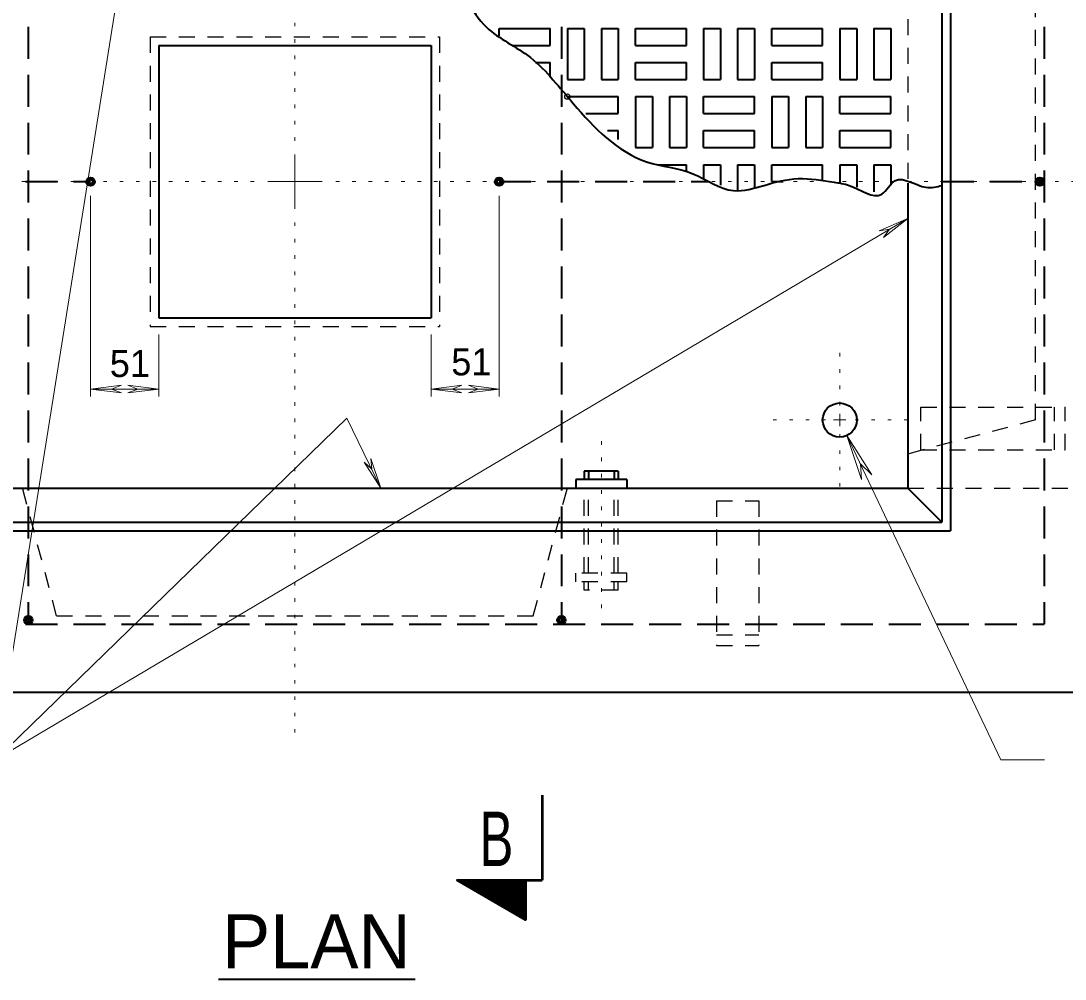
# Model space of a CAD drawing. Extents: x 312583 to 312854, y 144419 to 144597.
# Drawn here: x 312722.24 to 312751.63, y 144519.33 to 144546.3 of the extents above; entities that cross this region are included whole.
import ezdxf
from ezdxf.enums import TextEntityAlignment as Align

# ---------------------------------------------------------------- set-up
doc = ezdxf.new("R2010")
doc.units = 0
doc.header["$LTSCALE"] = 0.3
doc.header["$PDMODE"] = 32
doc.header["$PDSIZE"] = 0.15
for name, pattern in [('DOTTED', [1.5, 0.3, -1.2]), ('MEDIUM_DASHED', [4.5, 3, -1.5]), ('SHORT_DASHED', [2.7, 1.5, -1.2])]:
    doc.linetypes.add(name, pattern=pattern)
doc.layers.add('1', color=7, linetype='Continuous', lineweight=25)
doc.layers.add('2', color=7, linetype='Continuous', lineweight=13)

msp = doc.modelspace()

# ---------------------------------------------------------------- linework, layer by layer
at = {"layer": '1', "linetype": 'MEDIUM_DASHED', "lineweight": 40}
for p, q in [((312722.4474, 144554.2319), (312722.4474, 144529.3153)), ((312737.451, 144554.2319), (312737.451, 144529.3153)), ((312708.8697, 144541.7736), (312724.203, 144541.7736)), ((312735.703, 144541.7736), (312741.5987, 144541.7736)), ((312748.1614, 144541.7736), (312751.0364, 144541.7736)), ((312708.8697, 144529.3153), (312751.0364, 144529.3153))]:
    msp.add_line(p, q, dxfattribs=at)
at = {"layer": '1', "linetype": 'SHORT_DASHED'}
for p, q in [((312747.203, 144550.3986), (312747.203, 144541.7276)), ((312750.791, 144535.0653), (312750.791, 144548.4819)), ((312725.8744, 144545.8446), (312725.8744, 144537.6949)), ((312725.8744, 144537.6949), (312734.024, 144537.6949)), ((312747.5634, 144534.2219), (312747.5634, 144535.4256)), ((312747.5634, 144535.4256), (312751.6267, 144535.4256)), ((312751.3277, 144534.2219), (312751.3277, 144535.4256)), ((312751.6267, 144534.2219), (312751.6267, 144535.4256)), ((312750.791, 144535.0653), (312747.203, 144534.1069)), ((312747.5634, 144534.2219), (312751.6267, 144534.2219)), ((312723.2447, 144529.5529), (312722.2864, 144533.1486)), ((312736.6614, 144529.5529), (312737.6197, 144533.1486)), ((312738.095, 144530.7489), (312738.095, 144533.1486)), ((312738.2177, 144530.7489), (312738.2177, 144533.1486)), ((312738.9384, 144530.7489), (312738.9384, 144533.1486)), ((312739.0534, 144530.7489), (312739.0534, 144533.1486)), ((312747.203, 144533.1486), (312752.953, 144533.1486)), ((312741.8134, 144532.7883), (312743.0094, 144532.7883)), ((312741.8134, 144532.7883), (312741.8134, 144528.7173)), ((312743.0094, 144532.7883), (312743.0094, 144528.7173)), ((312739.291, 144530.7489), (312737.8574, 144530.7489)), ((312737.8574, 144530.5113), (312737.8574, 144530.7489)), ((312739.291, 144530.5113), (312739.291, 144530.7489)), ((312739.291, 144530.5113), (312737.8574, 144530.5113)), ((312738.095, 144530.2736), (312738.095, 144530.5113)), ((312739.0534, 144530.2736), (312738.095, 144530.2736)), ((312738.2177, 144530.2736), (312738.2177, 144530.5113)), ((312738.9384, 144530.2736), (312738.9384, 144530.5113)), ((312739.0534, 144530.2736), (312739.0534, 144530.5113)), ((312723.2447, 144529.5529), (312736.6614, 144529.5529)), ((312741.8134, 144529.0163), (312743.0094, 144529.0163)), ((312741.8134, 144528.7173), (312743.0094, 144528.7173))]:
    msp.add_line(p, q, dxfattribs=at)
at = {"layer": '1', "lineweight": 40}
for p, q in [((312735.703, 144546.0823), (312737.1367, 144546.0823)), ((312735.703, 144545.8753), (312735.703, 144546.0823)), ((312737.1367, 144545.6069), (312737.1367, 144546.0823)), ((312737.6197, 144546.0823), (312737.6197, 144544.6486)), ((312737.6197, 144546.0823), (312738.095, 144546.0823)), ((312738.095, 144546.0823), (312738.095, 144544.6486)), ((312738.578, 144546.0823), (312738.578, 144544.6486)), ((312738.578, 144546.0823), (312739.0534, 144546.0823)), ((312739.0534, 144546.0823), (312739.0534, 144544.6486)), ((312739.5364, 144546.0823), (312740.97, 144546.0823)), ((312739.5364, 144545.6069), (312739.5364, 144546.0823)), ((312740.97, 144545.6069), (312740.97, 144546.0823)), ((312741.453, 144546.0823), (312741.453, 144544.6486)), ((312741.453, 144546.0823), (312741.9284, 144546.0823)), ((312741.9284, 144546.0823), (312741.9284, 144544.6486)), ((312742.4114, 144546.0823), (312742.4114, 144544.6486)), ((312742.4114, 144546.0823), (312742.8867, 144546.0823)), ((312742.8867, 144546.0823), (312742.8867, 144544.6486)), ((312743.3697, 144546.0823), (312744.8034, 144546.0823)), ((312743.3697, 144545.6069), (312743.3697, 144546.0823)), ((312744.8034, 144545.6069), (312744.8034, 144546.0823)), ((312745.2864, 144546.0823), (312745.2864, 144544.6486)), ((312745.2864, 144546.0823), (312745.7617, 144546.0823)), ((312745.7617, 144546.0823), (312745.7617, 144544.6486)), ((312746.2447, 144546.0823), (312746.2447, 144544.6486)), ((312746.2447, 144546.0823), (312746.72, 144546.0823)), ((312746.72, 144546.0823), (312746.72, 144544.6486)), ((312726.1197, 144545.6069), (312726.1197, 144537.9403)), ((312726.1197, 144545.6069), (312733.7864, 144545.6069)), ((312733.7864, 144545.6069), (312733.7864, 144537.9403)), ((312736.094, 144545.6069), (312737.1367, 144545.6069)), ((312739.5364, 144545.6069), (312740.97, 144545.6069)), ((312743.3697, 144545.6069), (312744.8034, 144545.6069)), ((312736.7227, 144545.1239), (312737.1367, 144545.1239)), ((312737.1367, 144544.7099), (312737.1367, 144545.1239)), ((312739.5364, 144545.1239), (312740.97, 144545.1239)), ((312739.5364, 144544.6486), (312739.5364, 144545.1239)), ((312740.97, 144544.6486), (312740.97, 144545.1239)), ((312743.3697, 144545.1239), (312744.8034, 144545.1239)), ((312743.3697, 144544.6486), (312743.3697, 144545.1239)), ((312744.8034, 144544.6486), (312744.8034, 144545.1239)), ((312737.6197, 144544.6486), (312738.095, 144544.6486)), ((312738.578, 144544.6486), (312739.0534, 144544.6486)), ((312739.5364, 144544.6486), (312740.97, 144544.6486)), ((312741.453, 144544.6486), (312741.9284, 144544.6486)), ((312742.4114, 144544.6486), (312742.8867, 144544.6486)), ((312743.3697, 144544.6486), (312744.8034, 144544.6486)), ((312745.2864, 144544.6486), (312745.7617, 144544.6486)), ((312746.2447, 144544.6486), (312746.72, 144544.6486)), ((312737.6197, 144544.1656), (312739.0534, 144544.1656)), ((312739.0534, 144543.6903), (312739.0534, 144544.1656)), ((312739.5364, 144544.1656), (312739.5364, 144542.7319)), ((312739.5364, 144544.1656), (312740.0117, 144544.1656)), ((312740.0117, 144544.1656), (312740.0117, 144542.7319)), ((312740.4947, 144544.1656), (312740.4947, 144542.7319)), ((312740.4947, 144544.1656), (312740.97, 144544.1656)), ((312740.97, 144544.1656), (312740.97, 144542.7319)), ((312741.453, 144544.1656), (312742.8867, 144544.1656)), ((312741.453, 144543.6903), (312741.453, 144544.1656)), ((312742.8867, 144543.6903), (312742.8867, 144544.1656)), ((312743.3697, 144544.1656), (312743.3697, 144542.7319)), ((312743.3697, 144544.1656), (312743.845, 144544.1656)), ((312743.845, 144544.1656), (312743.845, 144542.7319)), ((312744.328, 144544.1656), (312744.328, 144542.7319)), ((312744.328, 144544.1656), (312744.8034, 144544.1656)), ((312744.8034, 144544.1656), (312744.8034, 144542.7319)), ((312745.2864, 144544.1656), (312746.72, 144544.1656)), ((312745.2864, 144543.6903), (312745.2864, 144544.1656)), ((312746.72, 144543.6903), (312746.72, 144544.1656)), ((312738.141, 144543.6903), (312739.0534, 144543.6903)), ((312741.453, 144543.6903), (312742.8867, 144543.6903)), ((312745.2864, 144543.6903), (312746.72, 144543.6903)), ((312738.7467, 144543.2073), (312739.0534, 144543.2073)), ((312739.0534, 144542.9619), (312739.0534, 144543.2073)), ((312741.453, 144543.2073), (312742.8867, 144543.2073)), ((312741.453, 144542.7319), (312741.453, 144543.2073)), ((312742.8867, 144542.7319), (312742.8867, 144543.2073)), ((312745.2864, 144543.2073), (312746.72, 144543.2073)), ((312745.2864, 144542.7319), (312745.2864, 144543.2073)), ((312746.72, 144542.7319), (312746.72, 144543.2073)), ((312739.5364, 144542.7319), (312740.0117, 144542.7319)), ((312740.4947, 144542.7319), (312740.97, 144542.7319)), ((312741.453, 144542.7319), (312742.8867, 144542.7319)), ((312743.3697, 144542.7319), (312743.845, 144542.7319)), ((312744.328, 144542.7319), (312744.8034, 144542.7319)), ((312745.2864, 144542.7319), (312746.72, 144542.7319)), ((312740.1804, 144542.2489), (312740.97, 144542.2489)), ((312740.97, 144542.0419), (312740.97, 144542.2489)), ((312741.453, 144542.2489), (312741.453, 144541.8733)), ((312741.453, 144542.2489), (312741.9284, 144542.2489)), ((312741.9284, 144542.2489), (312741.9284, 144541.6739)), ((312742.4114, 144542.2489), (312742.4114, 144541.5359)), ((312742.4114, 144542.2489), (312742.8867, 144542.2489)), ((312742.8867, 144542.2489), (312742.8867, 144541.6203)), ((312743.3697, 144542.2489), (312744.8034, 144542.2489)), ((312743.3697, 144541.7736), (312743.3697, 144542.2489)), ((312744.8034, 144541.7889), (312744.8034, 144542.2489)), ((312745.2864, 144542.2489), (312745.2864, 144541.7276)), ((312745.2864, 144542.2489), (312745.7617, 144542.2489)), ((312745.7617, 144542.2489), (312745.7617, 144541.6126)), ((312746.2447, 144542.2489), (312746.2447, 144541.4823)), ((312746.2447, 144542.2489), (312746.72, 144542.2489)), ((312746.72, 144542.2489), (312746.72, 144541.6816)), ((312743.3697, 144541.7736), (312743.6917, 144541.7736)), ((312747.203, 144541.7276), (312747.203, 144533.1486)), ((312726.1197, 144537.9403), (312733.7864, 144537.9403)), ((312739.0534, 144533.6239), (312738.095, 144533.6239)), ((312738.095, 144533.6239), (312738.095, 144533.3863)), ((312738.2177, 144533.6239), (312738.2177, 144533.3863)), ((312738.9384, 144533.6239), (312738.9384, 144533.3863)), ((312739.0534, 144533.6239), (312739.0534, 144533.3863)), ((312739.291, 144533.3863), (312737.8574, 144533.3863)), ((312737.8574, 144533.3863), (312737.8574, 144533.1486)), ((312739.291, 144533.3863), (312739.291, 144533.1486)), ((312747.203, 144533.1486), (312748.1614, 144532.1903)), ((312711.7447, 144532.1903), (312748.1614, 144532.1903)), ((312711.4994, 144531.9449), (312748.399, 144531.9449)), ((312706.953, 144527.3986), (312752.953, 144527.3986))]:
    msp.add_line(p, q, dxfattribs=at)
at = {"layer": '1', "linetype": 'DOTTED', "lineweight": 13}
msp.add_line((312738.578, 144529.7676), (312738.578, 144534.5056), dxfattribs=at)
at = {"layer": '1', "lineweight": 53}
for p in [(312736.9144, 144524.5006), (312736.439, 144522.1086)]:
    msp.add_line(p, (312736.9144, 144522.1086), dxfattribs=at)
at = {"layer": '1', "lineweight": 35}
for p, q in [((312734.5377, 144522.1086), (312734.5377, 144522.0933)), ((312734.5684, 144522.1086), (312734.5607, 144522.0856)), ((312734.599, 144522.1086), (312734.576, 144522.0703)), ((312734.622, 144522.1086), (312734.599, 144522.0626)), ((312734.6527, 144522.1086), (312734.622, 144522.0473)), ((312734.6757, 144522.1086), (312734.6374, 144522.0396)), ((312734.7064, 144522.1086), (312734.6604, 144522.0243)), ((312734.737, 144522.1086), (312734.6834, 144522.0166)), ((312734.7677, 144522.1086), (312734.6987, 144522.0013)), ((312734.7907, 144522.1086), (312734.7217, 144521.9936)), ((312734.8137, 144522.1086), (312734.7447, 144521.9783)), ((312734.8444, 144522.1086), (312734.7677, 144521.9706)), ((312734.8674, 144522.1086), (312734.783, 144521.9553)), ((312734.898, 144522.1086), (312734.806, 144521.9399)), ((312734.9287, 144522.1086), (312734.829, 144521.9323)), ((312734.9594, 144522.1086), (312734.8444, 144521.9169)), ((312734.9824, 144522.1086), (312734.8674, 144521.9016)), ((312735.013, 144522.1086), (312734.8904, 144521.8939)), ((312735.036, 144522.1086), (312734.9057, 144521.8786)), ((312735.0667, 144522.1086), (312734.9287, 144521.8709)), ((312735.0974, 144522.1086), (312734.9517, 144521.8556)), ((312735.1204, 144522.1086), (312734.967, 144521.8479)), ((312735.151, 144522.1086), (312734.9977, 144521.8326)), ((312735.174, 144522.1086), (312735.013, 144521.8249)), ((312735.2047, 144522.1086), (312735.036, 144521.8096)), ((312735.2354, 144522.1086), (312735.059, 144521.8019)), ((312735.2584, 144522.1086), (312735.0744, 144521.7866)), ((312735.289, 144522.1086), (312735.0974, 144521.7789)), ((312735.312, 144522.1086), (312735.1204, 144521.7636)), ((312735.3427, 144522.1086), (312735.1357, 144521.7483)), ((312735.3657, 144522.1086), (312735.1587, 144521.7406)), ((312735.3964, 144522.1086), (312735.1817, 144521.7253)), ((312735.427, 144522.1086), (312735.197, 144521.7099)), ((312735.4577, 144522.1086), (312735.22, 144521.7023)), ((312735.4807, 144522.1086), (312735.243, 144521.6869)), ((312735.5037, 144522.1086), (312735.266, 144521.6793)), ((312735.5344, 144522.1086), (312735.2814, 144521.6639)), ((312735.565, 144522.1086), (312735.3044, 144521.6563)), ((312735.588, 144522.1086), (312735.3274, 144521.6409)), ((312735.6187, 144522.1086), (312735.3427, 144521.6333)), ((312735.6494, 144522.1086), (312735.3657, 144521.6179)), ((312735.6724, 144522.1086), (312735.3887, 144521.6103)), ((312735.703, 144522.1086), (312735.404, 144521.5949)), ((312735.7337, 144522.1086), (312735.427, 144521.5873)), ((312735.7567, 144522.1086), (312735.45, 144521.5719)), ((312735.7874, 144522.1009), (312735.4654, 144521.5566)), ((312735.8104, 144522.1086), (312735.496, 144521.5489)), ((312735.841, 144522.1086), (312735.5114, 144521.5336)), ((312735.864, 144522.1086), (312735.5344, 144521.5259)), ((312735.8947, 144522.1086), (312735.5574, 144521.5106)), ((312735.9254, 144522.1086), (312735.5727, 144521.5029)), ((312735.956, 144522.1086), (312735.5957, 144521.4876)), ((312735.979, 144522.1086), (312735.6187, 144521.4799)), ((312736.002, 144522.1086), (312735.634, 144521.4646)), ((312736.0327, 144522.1009), (312735.657, 144521.4569)), ((312736.0634, 144522.1086), (312735.68, 144521.4416)), ((312736.0864, 144522.1086), (312735.6954, 144521.4339)), ((312736.117, 144522.1086), (312735.7184, 144521.4186)), ((312736.1477, 144522.1086), (312735.7414, 144521.4033)), ((312736.1707, 144522.1086), (312735.7644, 144521.3956)), ((312736.2014, 144522.1086), (312735.7797, 144521.3803)), ((312736.232, 144522.1086), (312735.8027, 144521.3649)), ((312736.255, 144522.1009), (312735.8257, 144521.3573)), ((312736.2857, 144522.1009), (312735.841, 144521.3419)), ((312736.3087, 144522.1086), (312735.864, 144521.3343)), ((312736.3394, 144522.1086), (312735.887, 144521.3189)), ((312736.3624, 144522.1086), (312735.9024, 144521.3113)), ((312736.393, 144522.1086), (312735.9254, 144521.2959)), ((312736.4237, 144522.1086), (312735.9484, 144521.2883)), ((312736.439, 144522.0856), (312735.9637, 144521.2729)), ((312736.439, 144522.0319), (312735.9944, 144521.2653)), ((312736.439, 144521.9936), (312736.0097, 144521.2499)), ((312736.439, 144521.9399), (312736.0327, 144521.2423)), ((312736.439, 144521.8939), (312736.0557, 144521.2269)), ((312736.439, 144521.8479), (312736.071, 144521.2116)), ((312736.439, 144521.8019), (312736.094, 144521.2039)), ((312736.439, 144521.7483), (312736.117, 144521.1886)), ((312736.439, 144521.7023), (312736.1324, 144521.1733)), ((312736.439, 144521.6563), (312736.1554, 144521.1656)), ((312736.439, 144521.6026), (312736.1707, 144521.1503)), ((312736.439, 144521.5566), (312736.1937, 144521.1426)), ((312736.439, 144521.5106), (312736.2167, 144521.1273)), ((312736.439, 144521.4569), (312736.232, 144521.1196)), ((312736.439, 144521.4109), (312736.2627, 144521.1043)), ((312736.439, 144521.3649), (312736.278, 144521.0966)), ((312736.439, 144521.3189), (312736.301, 144521.0813)), ((312736.439, 144521.2653), (312736.324, 144521.0736)), ((312736.439, 144521.2269), (312736.3394, 144521.0583)), ((312736.439, 144521.1733), (312736.3624, 144521.0506)), ((312736.439, 144521.1273), (312736.3854, 144521.0353)), ((312736.439, 144521.0736), (312736.4007, 144521.0199)), ((312736.439, 144521.0276), (312736.4237, 144521.0123))]:
    msp.add_line(p, q, dxfattribs=at)
at = {"layer": '1', "linetype": 'MEDIUM_DASHED', "lineweight": 40}
msp.add_lwpolyline([(312709.1074, 144554.2319), (312751.0364, 144554.2319), (312751.0364, 144529.3153)], dxfattribs=at)
at = {"layer": '1', "lineweight": 40}
for points in [[(312711.4994, 144551.5946), (312748.399, 144551.5946), (312748.399, 144531.9449)], [(312711.7447, 144551.3569), (312748.1614, 144551.3569), (312748.1614, 144532.1903)], [(312712.703, 144550.3986), (312712.703, 144533.1486), (312747.203, 144533.1486)]]:
    msp.add_lwpolyline(points, dxfattribs=at)
at = {"layer": '1', "linetype": 'SHORT_DASHED'}
msp.add_lwpolyline([(312725.8744, 144545.8446), (312734.024, 144545.8446), (312734.024, 144537.6949)], dxfattribs=at)
at = {"layer": '1', "lineweight": 53}
msp.add_lwpolyline([(312736.439, 144522.1086), (312736.439, 144520.9969), (312734.5224, 144522.1086)], close=True, dxfattribs=at)
at = {"layer": '1', "lineweight": 40}
for centre, radius in [((312724.2002, 144541.7707), 0.1198), ((312724.2002, 144541.7707), 0.0838), ((312724.2002, 144541.7707), 0.0587), ((312735.7002, 144541.7707), 0.1198), ((312735.7002, 144541.7707), 0.0838), ((312735.7002, 144541.7707), 0.0587), ((312750.9137, 144541.7707), 0.1198), ((312750.9137, 144541.7707), 0.0838), ((312750.9137, 144541.7707), 0.0587), ((312745.2835, 144535.0624), 0.4792), ((312722.4502, 144529.4322), 0.1198), ((312722.4502, 144529.4322), 0.0838), ((312722.4502, 144529.4322), 0.0587), ((312737.4501, 144529.4322), 0.1198), ((312737.4501, 144529.4322), 0.0838), ((312737.4501, 144529.4322), 0.0587)]:
    msp.add_circle(centre, radius, dxfattribs=at)
msp.add_spline([(312733.564, 144551.5946), (312733.9014, 144550.7743), (312733.8094, 144549.3866), (312734.3844, 144547.7996), (312735.3427, 144546.1206), (312736.5847, 144545.2619), (312737.2134, 144544.6409), (312737.7884, 144543.9663), (312739.8507, 144542.3333), (312741.1464, 144541.9959), (312742.2964, 144541.5206), (312743.155, 144541.6663), (312744.1134, 144541.8579), (312745.1254, 144541.7583), (312745.5547, 144541.6663), (312746.467, 144541.4209), (312746.8504, 144541.8043), (312747.709, 144541.6126), (312748.1614, 144541.6663)], degree=3, dxfattribs=at)
at = {"layer": '1'}
msp.add_point((312737.6197, 144544.1656), dxfattribs=at)
at = {"layer": '2', "linetype": 'DOTTED'}
for p, q in [((312729.953, 144542.9236), (312729.953, 144556.6623)), ((312728.803, 144541.7736), (312705.5117, 144541.7736)), ((312731.103, 144541.7736), (312752.056, 144541.7736)), ((312729.953, 144540.6236), (312729.953, 144526.2256)), ((312745.2864, 144535.4716), (312745.2864, 144537.0279)), ((312744.8877, 144535.0653), (312743.316, 144535.0653)), ((312745.7157, 144535.0653), (312747.249, 144535.0653)), ((312745.2864, 144534.6666), (312745.2864, 144533.0949))]:
    msp.add_line(p, q, dxfattribs=at)
at = {"layer": '2'}
for p, q in [((312729.953, 144541.7736), (312729.953, 144542.5403)), ((312729.953, 144541.7736), (312729.1864, 144541.7736)), ((312729.953, 144541.7736), (312730.7197, 144541.7736)), ((312729.953, 144541.7736), (312729.953, 144541.0069)), ((312724.203, 144535.7246), (312724.203, 144541.3749)), ((312735.703, 144535.7246), (312735.703, 144541.3749)), ((312721.5197, 144525.4973), (312747.203, 144540.7386)), ((312747.203, 144540.7386), (312746.398, 144540.3859)), ((312747.203, 144540.7386), (312746.513, 144540.2019)), ((312746.398, 144540.3859), (312746.6894, 144540.4319)), ((312746.513, 144540.2019), (312746.6894, 144540.4319)), ((312726.1197, 144535.7246), (312726.1197, 144537.4726)), ((312733.7864, 144535.7246), (312733.7864, 144537.4726)), ((312724.203, 144535.9316), (312725.0694, 144536.0389)), ((312724.203, 144535.9316), (312726.1197, 144535.9316)), ((312724.203, 144535.9316), (312725.0694, 144535.8243)), ((312725.0694, 144536.0389), (312724.7934, 144535.9316)), ((312725.0694, 144535.8243), (312724.7934, 144535.9316)), ((312725.2534, 144536.0389), (312725.5294, 144535.9316)), ((312726.1197, 144535.9316), (312725.2534, 144536.0389)), ((312725.2534, 144535.8243), (312725.5294, 144535.9316)), ((312726.1197, 144535.9316), (312725.2534, 144535.8243)), ((312733.7864, 144535.9316), (312734.6527, 144536.0389)), ((312733.7864, 144535.9316), (312735.703, 144535.9316)), ((312733.7864, 144535.9316), (312734.6527, 144535.8243)), ((312734.6527, 144536.0389), (312734.3767, 144535.9316)), ((312734.6527, 144535.8243), (312734.3767, 144535.9316)), ((312734.8367, 144536.0389), (312735.1127, 144535.9316)), ((312735.703, 144535.9316), (312734.8367, 144536.0389)), ((312734.8367, 144535.8243), (312735.1127, 144535.9316)), ((312735.703, 144535.9316), (312734.8367, 144535.8243)), ((312745.2864, 144535.0653), (312745.11, 144535.0653)), ((312745.2864, 144535.0653), (312745.2864, 144535.2339)), ((312745.2864, 144535.0653), (312745.455, 144535.0653)), ((312745.2864, 144535.0653), (312745.2864, 144534.8889)), ((312745.4857, 144534.6283), (312749.8174, 144525.4973)), ((312745.4857, 144534.6283), (312745.8997, 144533.3863)), ((312745.4857, 144534.6283), (312746.191, 144533.5243)), ((312731.9004, 144533.8769), (312732.115, 144533.6776)), ((312732.368, 144533.1486), (312731.9004, 144533.8769)), ((312732.092, 144533.9766), (312732.115, 144533.6776)), ((312732.368, 144533.1486), (312732.092, 144533.9766)), ((312745.8997, 144533.3863), (312745.869, 144533.8309)), ((312746.191, 144533.5243), (312745.869, 144533.8309)), ((312751.0517, 144525.4973), (312749.8174, 144525.4973))]:
    msp.add_line(p, q, dxfattribs=at)
at = {"layer": '2', "lineweight": 40}
msp.add_line((312727.8064, 144519.3256), (312733.3391, 144519.3256), dxfattribs=at)
at = {"layer": '2'}
msp.add_lwpolyline([(312725.491, 144550.3986), (312721.5197, 144525.4973), (312731.4174, 144535.1189), (312732.368, 144533.1486)], dxfattribs=at)

# ---------------------------------------------------------------- texts
at = {"layer": '1', "width": 0.7}
msp.add_text('B', height=1.533, dxfattribs=at).set_placement((312735.6225, 144522.5073), align=Align.CENTER)
at = {"layer": '2'}
for p in [(312724.7417, 144536.273), (312734.3527, 144536.3199)]:
    msp.add_text('51 ', height=0.76, dxfattribs=at).set_placement(p)
msp.add_text('PLAN', height=1.52, dxfattribs=at).set_placement((312730.5554, 144519.6305), align=Align.CENTER)

doc.saveas('drawing.dxf')
